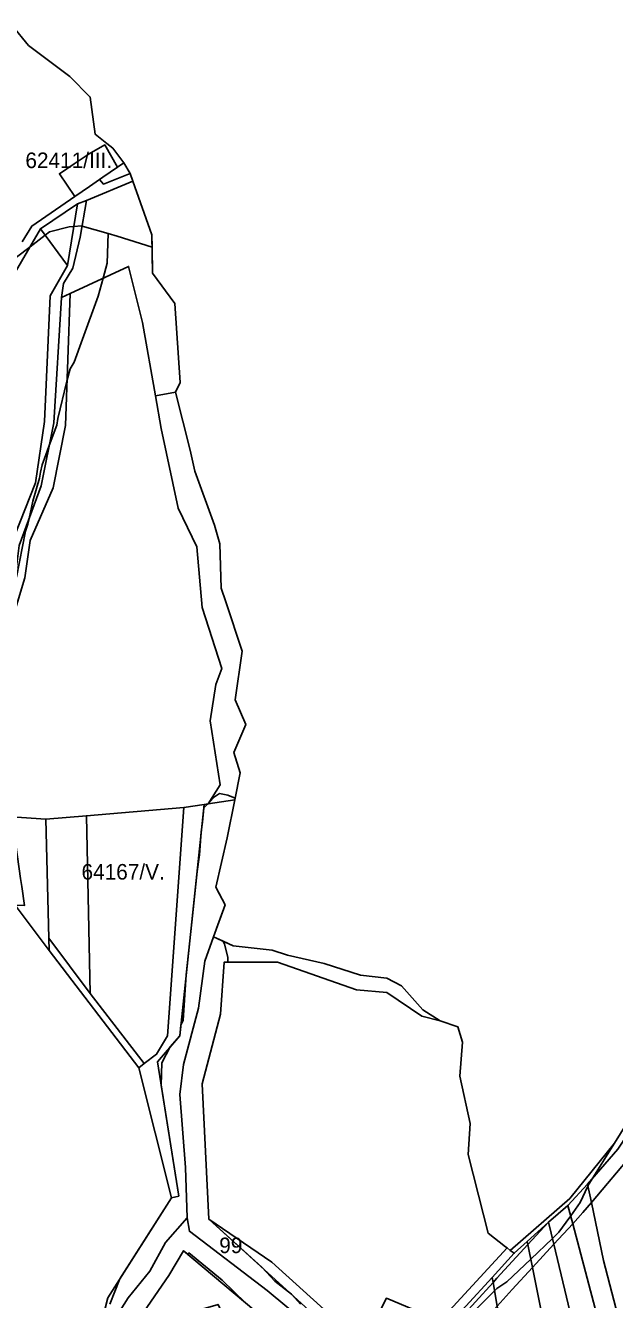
# Model space of a CAD drawing. Extents: x -502026 to -497664, y -1143484 to -1138019.
# Drawn here: x -499524 to -499221, y -1138994 to -1138339 of the extents above; entities that cross this region are included whole.
import ezdxf

# ---------------------------------------------------------------- set-up
doc = ezdxf.new("R2010")
doc.units = 0
for name, color, linetype in [('25', 7, 'Continuous'), ('37', 7, 'Continuous'), ('43', 7, 'Continuous'), ('55', 7, 'Continuous'), ('62', 7, 'Continuous'), ('7', 7, 'Continuous')]:
    doc.layers.add(name, color=color, linetype=linetype)

msp = doc.modelspace()

# ---------------------------------------------------------------- linework, layer by layer
at = {"layer": '25'}
msp.add_lwpolyline([(-499530.72, -1138338.78), (-499522.27, -1138349.07), (-499501.03, -1138365.08), (-499490.59, -1138375.59), (-499488.02, -1138394.73), (-499481.95, -1138399.48), (-499478.99, -1138401.8), (-499473.32, -1138409.43), (-499476.51, -1138411.63), (-499483.08, -1138400.19), (-499491.04, -1138404.76), (-499498.86, -1138409.97), (-499506.45, -1138415.02), (-499498.42, -1138426.7), (-499520.54, -1138441.91), (-499525.63, -1138450.02)], dxfattribs=at)
for points in [[(-499470.03, -1138414.97), (-499483.78, -1138420.33), (-499485.83, -1138418.04), (-499484.1, -1138416.85), (-499476.51, -1138411.63), (-499473.32, -1138409.43)], [(-499446.67, -1138527.4), (-499456.93, -1138529.27), (-499463.7, -1138491.52), (-499470.85, -1138462.66), (-499500.91, -1138476.52), (-499505.39, -1138478.58), (-499504.36, -1138471.49), (-499499.51, -1138463.57), (-499495.68, -1138447.61), (-499492.56, -1138428.73), (-499468.59, -1138418.83), (-499458.82, -1138446.46), (-499458.5, -1138466.16), (-499446.96, -1138481.75), (-499444.3, -1138522.32)], [(-499448.8, -1138941.59), (-499465.58, -1138874.76), (-499462.75, -1138872.57), (-499456.42, -1138867.8), (-499450.74, -1138858.41), (-499442.38, -1138740.98), (-499431.91, -1138739.41), (-499444.5, -1138858.39), (-499456.02, -1138871.76), (-499445.03, -1138940.74)], [(-499513.48, -1138746.91), (-499511.89, -1138808.1), (-499511.73, -1138814.39), (-499529.18, -1138791.22), (-499524.4, -1138791.35), (-499525.8, -1138781.59), (-499526.38, -1138777.45), (-499528.82, -1138760.16), (-499530.87, -1138745.67)], [(-499490.59, -1138836.55), (-499511.89, -1138808.1), (-499513.48, -1138746.91), (-499492.56, -1138745.17)]]:
    msp.add_lwpolyline(points, close=True, dxfattribs=at)
at = {"layer": '37'}
for points in [[(-499524.27, -1138622.83), (-499521.46, -1138603.68), (-499509.59, -1138576.6), (-499503.34, -1138544.42), (-499500.91, -1138476.52), (-499470.85, -1138462.66), (-499463.7, -1138491.52), (-499456.93, -1138529.27), (-499454.04, -1138546.01), (-499445.32, -1138587.05), (-499435.65, -1138606.87), (-499432.96, -1138638.09), (-499422.92, -1138669.37), (-499425.89, -1138677.59), (-499428.78, -1138696.38), (-499423.73, -1138729.2), (-499429.8, -1138739.09), (-499431.91, -1138739.41), (-499442.38, -1138740.98), (-499492.56, -1138745.17), (-499513.48, -1138746.91), (-499530.87, -1138745.67)], [(-499368.53, -1139000.61), (-499397.19, -1138974.7), (-499429.54, -1138952.6), (-499432.99, -1138883), (-499423.57, -1138847.18), (-499421.6, -1138820.45), (-499394.19, -1138820.45), (-499353.59, -1138834.76), (-499337.92, -1138836.13), (-499319.93, -1138848.22), (-499310.56, -1138850.57), (-499301.36, -1138853.71), (-499299, -1138861.57), (-499300.4, -1138879.14), (-499295.11, -1138903.36), (-499296.16, -1138919.34), (-499288.26, -1138950.44), (-499285.71, -1138959.88), (-499276.87, -1138966.81), (-499276.08, -1138967.42), (-499313.71, -1139008.25)], [(-499323.82, -1138999.2), (-499338.15, -1138993.28), (-499347.75, -1139011.93)]]:
    msp.add_lwpolyline(points, dxfattribs=at)
for points in [[(-499552.1, -1138790.55), (-499529.18, -1138791.22), (-499511.73, -1138814.39), (-499465.58, -1138874.76), (-499448.8, -1138941.59), (-499481.51, -1138993.07), (-499490.65, -1139028.16), (-499509.08, -1139023.11), (-499518.14, -1139024.19), (-499536.05, -1139033.29), (-499543.48, -1138994.87), (-499553.65, -1138932.11), (-499564.96, -1138868.79), (-499577.25, -1138815.93), (-499591.11, -1138774.54), (-499588.16, -1138761.99), (-499580.14, -1138748.95), (-499566.24, -1138743.1), (-499558.38, -1138790.37)], [(-499462.75, -1138872.57), (-499490.59, -1138836.55), (-499492.56, -1138745.17), (-499442.38, -1138740.98), (-499450.74, -1138858.41), (-499456.42, -1138867.8)], [(-499490.59, -1138836.55), (-499462.75, -1138872.57), (-499465.58, -1138874.76), (-499511.73, -1138814.39), (-499511.89, -1138808.1)], [(-499313.71, -1139008.25), (-499332.28, -1139026.34), (-499346.28, -1139036.83), (-499366.75, -1139009.62), (-499429.54, -1138952.6), (-499397.19, -1138974.7), (-499368.53, -1139000.61), (-499347.75, -1139011.93), (-499338.15, -1138993.28), (-499323.82, -1138999.2), (-499325.79, -1139003.8)], [(-499401.1, -1139003.69), (-499418.99, -1139008.62), (-499424.81, -1138996.42), (-499456.81, -1139005.71), (-499468.66, -1139018.24), (-499473.7, -1139021.67), (-499470.57, -1139011.19), (-499450.09, -1138981.53), (-499442.49, -1138968.89)]]:
    msp.add_lwpolyline(points, close=True, dxfattribs=at)
at = {"layer": '43'}
for points in [[(-499537.01, -1138745.37), (-499548.75, -1138698.77), (-499546.8, -1138675.05), (-499544.76, -1138664.32), (-499536.74, -1138644.34), (-499529, -1138621.3), (-499527.08, -1138606.23), (-499515.85, -1138575.58), (-499509.34, -1138543.14), (-499505.39, -1138478.58), (-499500.91, -1138476.52), (-499503.34, -1138544.42), (-499509.59, -1138576.6), (-499521.46, -1138603.68), (-499524.27, -1138622.83), (-499528.49, -1138637.04), (-499543.1, -1138676.2), (-499544.51, -1138699.06)], [(-499416.15, -1138737.03), (-499429.8, -1138739.09), (-499423.73, -1138729.2), (-499428.78, -1138696.38), (-499425.89, -1138677.59), (-499422.92, -1138669.37), (-499432.96, -1138638.09), (-499435.65, -1138606.87), (-499445.32, -1138587.05), (-499454.04, -1138546.01), (-499456.93, -1138529.27), (-499446.67, -1138527.4), (-499439.13, -1138557.09), (-499436.76, -1138567.96), (-499426.61, -1138595.74), (-499423.9, -1138605.27), (-499423.22, -1138628.12), (-499420.78, -1138635.17), (-499412.39, -1138660.5), (-499415.96, -1138685.51), (-499410.57, -1138698.3), (-499416.73, -1138712.67), (-499413.35, -1138723.05)], [(-499350.25, -1139039.81), (-499353.46, -1139042.22), (-499375.14, -1139022.61), (-499401.1, -1139003.69), (-499442.49, -1138968.89), (-499450.09, -1138981.53), (-499470.57, -1139011.19), (-499473.7, -1139021.67), (-499487.23, -1139030.88), (-499485.67, -1139023.72), (-499480.41, -1139008.06), (-499471.01, -1138993.06), (-499459.94, -1138979.29), (-499451.77, -1138964.63), (-499440.6, -1138951.93), (-499439.5, -1138958.87), (-499399.56, -1138989.3), (-499370.11, -1139013.65)]]:
    msp.add_lwpolyline(points, close=True, dxfattribs=at)
for points in [[(-499490.65, -1139028.16), (-499481.51, -1138993.07), (-499448.8, -1138941.59), (-499445.03, -1138940.74), (-499456.02, -1138871.76), (-499444.5, -1138858.39), (-499431.91, -1138739.41), (-499429.8, -1138739.09), (-499416.15, -1138737.03), (-499420.04, -1138756.44), (-499425.86, -1138781.93), (-499421.19, -1138790.99), (-499427.15, -1138807.36), (-499431.53, -1138819.97), (-499434.87, -1138844.05), (-499442.58, -1138873.14), (-499444.47, -1138888.57), (-499441.47, -1138925.97), (-499440.6, -1138951.93), (-499451.77, -1138964.63), (-499459.94, -1138979.29), (-499471.01, -1138993.06), (-499480.41, -1139008.06)], [(-499370.11, -1139013.65), (-499399.56, -1138989.3), (-499439.5, -1138958.87), (-499440.6, -1138951.93), (-499441.47, -1138925.97), (-499444.47, -1138888.57), (-499442.58, -1138873.14), (-499434.87, -1138844.05), (-499431.53, -1138819.97), (-499427.15, -1138807.36), (-499417.07, -1138812.03), (-499396.87, -1138814.31), (-499389, -1138816.85), (-499370.21, -1138821.17), (-499351.49, -1138827.06), (-499337.99, -1138828.75), (-499330.46, -1138832.65), (-499319.36, -1138844.97), (-499310.56, -1138850.57), (-499319.93, -1138848.22), (-499337.92, -1138836.13), (-499353.59, -1138834.76), (-499394.19, -1138820.45), (-499421.6, -1138820.45), (-499423.57, -1138847.18), (-499432.99, -1138883), (-499429.54, -1138952.6), (-499366.75, -1139009.62)]]:
    msp.add_lwpolyline(points, dxfattribs=at)
at = {"layer": '55'}
for points in [[(-499476.51, -1138411.63), (-499484.1, -1138416.85), (-499485.83, -1138418.04), (-499490.91, -1138421.53), (-499498.42, -1138426.7), (-499506.45, -1138415.02), (-499498.86, -1138409.97), (-499491.04, -1138404.76), (-499483.08, -1138400.19)], [(-499502.32, -1138462.17), (-499516.1, -1138443.28), (-499497.07, -1138430.58)], [(-499502.32, -1138462.17), (-499511.25, -1138477.75), (-499514.06, -1138542.37), (-499518.66, -1138574.05), (-499534.87, -1138614.79), (-499534.99, -1138618.61), (-499538.24, -1138616.75), (-499545.72, -1138612.49), (-499545.21, -1138605.34), (-499586.97, -1138559.44), (-499565.83, -1138540.79), (-499556.38, -1138512.27), (-499539.85, -1138477.89), (-499531.49, -1138469.59), (-499516.1, -1138443.28)], [(-499211.45, -1138919.07), (-499232.65, -1138944.1), (-499234.61, -1138934.63), (-499219.06, -1138916.54), (-499214.15, -1138909.07)], [(-499232.65, -1138944.1), (-499236.99, -1138949.22), (-499242.28, -1138954.93), (-499244.75, -1138945.59), (-499234.61, -1138934.63)], [(-499242.28, -1138954.93), (-499252.06, -1138965.49), (-499254.79, -1138954.09), (-499244.75, -1138945.59)], [(-499265.41, -1138965.63), (-499265.71, -1138964.12), (-499254.79, -1138954.09)], [(-499252.06, -1138965.49), (-499263.04, -1138977.44), (-499265.41, -1138965.63), (-499254.79, -1138954.09)], [(-499265.41, -1138965.63), (-499281.32, -1138982.93), (-499283.29, -1138985.11), (-499283.72, -1138982.6), (-499272.34, -1138970.18), (-499265.71, -1138964.12)], [(-499263.04, -1138977.44), (-499273.5, -1138988.83), (-499281.13, -1138997.36), (-499283.29, -1138985.11), (-499281.32, -1138982.93), (-499265.41, -1138965.63)], [(-499283.29, -1138985.11), (-499310.42, -1139015.06), (-499310.79, -1139012.14), (-499283.72, -1138982.6)], [(-499281.13, -1138997.36), (-499306, -1139025.17), (-499308.75, -1139028.21), (-499310.42, -1139015.06), (-499283.29, -1138985.11)]]:
    msp.add_lwpolyline(points, close=True, dxfattribs=at)
for points in [[(-499525.63, -1138450.02), (-499520.54, -1138441.91), (-499498.42, -1138426.7), (-499490.91, -1138421.53), (-499485.83, -1138418.04), (-499483.78, -1138420.33), (-499470.03, -1138414.97), (-499468.59, -1138418.83), (-499492.56, -1138428.73), (-499497.07, -1138430.58), (-499516.1, -1138443.28), (-499531.49, -1138469.59)], [(-499534.87, -1138614.79), (-499518.66, -1138574.05), (-499514.06, -1138542.37), (-499511.25, -1138477.75), (-499502.32, -1138462.17), (-499497.07, -1138430.58), (-499492.56, -1138428.73), (-499495.68, -1138447.61), (-499499.51, -1138463.57), (-499504.36, -1138471.49), (-499505.39, -1138478.58), (-499509.34, -1138543.14), (-499515.85, -1138575.58), (-499527.08, -1138606.23)], [(-499219.06, -1138916.54), (-499234.61, -1138934.63), (-499244.75, -1138945.59), (-499254.79, -1138954.09), (-499265.71, -1138964.12), (-499272.34, -1138970.18), (-499274.39, -1138968.75), (-499243.81, -1138942.05), (-499220.78, -1138913.59), (-499210.6, -1138897.3)], [(-499313.71, -1139008.25), (-499276.08, -1138967.42), (-499274.39, -1138968.75), (-499272.34, -1138970.18), (-499283.72, -1138982.6), (-499310.79, -1139012.14)]]:
    msp.add_lwpolyline(points, dxfattribs=at)
at = {"layer": '62'}
for points in [[(-499530.72, -1138338.78), (-499522.27, -1138349.07), (-499501.03, -1138365.08), (-499490.59, -1138375.59), (-499488.02, -1138394.73), (-499481.95, -1138399.48), (-499478.99, -1138401.8), (-499473.32, -1138409.43), (-499470.03, -1138414.97), (-499468.59, -1138418.83), (-499458.82, -1138446.46), (-499458.72, -1138452.71), (-499476.7, -1138447.19), (-499481.41, -1138445.75), (-499494.74, -1138441.95), (-499495, -1138441.87), (-499499, -1138442.19), (-499501.37, -1138442.37), (-499511.56, -1138444.87), (-499513.72, -1138446.54), (-499521.54, -1138452.58), (-499528.56, -1138458)], [(-499528.56, -1138458), (-499521.54, -1138452.58), (-499513.72, -1138446.54), (-499511.56, -1138444.87), (-499501.37, -1138442.37), (-499499, -1138442.19), (-499495, -1138441.87), (-499494.74, -1138441.95), (-499481.41, -1138445.75), (-499481.81, -1138461), (-499483.93, -1138468.69), (-499486.5, -1138478), (-499494.56, -1138500.12), (-499498.81, -1138512), (-499500.94, -1138515.37), (-499502.53, -1138521.74), (-499507.31, -1138540.87), (-499507.75, -1138544.25), (-499511.69, -1138554.83), (-499513.43, -1138559.52), (-499515.37, -1138564.75), (-499516.09, -1138568.5), (-499516.66, -1138571.5), (-499520.06, -1138583.37), (-499521.95, -1138592.23), (-499522.59, -1138595.25), (-499523.87, -1138598.75), (-499528.56, -1138622.5)], [(-499528.56, -1138622.5), (-499523.87, -1138598.75), (-499522.59, -1138595.25), (-499521.95, -1138592.23), (-499520.06, -1138583.37), (-499516.66, -1138571.5), (-499516.09, -1138568.5), (-499515.37, -1138564.75), (-499513.43, -1138559.52), (-499511.69, -1138554.83), (-499507.75, -1138544.25), (-499507.31, -1138540.87), (-499502.53, -1138521.74), (-499500.94, -1138515.37), (-499498.81, -1138512), (-499494.56, -1138500.12), (-499486.5, -1138478), (-499483.93, -1138468.69), (-499481.81, -1138461), (-499481.41, -1138445.75), (-499476.7, -1138447.19), (-499458.72, -1138452.71), (-499458.5, -1138466.16), (-499446.96, -1138481.75), (-499444.3, -1138522.32), (-499446.67, -1138527.4), (-499439.13, -1138557.09), (-499436.76, -1138567.96), (-499426.61, -1138595.74), (-499423.9, -1138605.27), (-499423.22, -1138628.12), (-499420.78, -1138635.17), (-499412.39, -1138660.5), (-499415.96, -1138685.51), (-499410.57, -1138698.3), (-499416.73, -1138712.67), (-499413.35, -1138723.05), (-499415.97, -1138736.14), (-499419.78, -1138734.62), (-499424.03, -1138733.75), (-499426.59, -1138735.5), (-499429.23, -1138738.17), (-499429.8, -1138739.09), (-499430.21, -1138739.15), (-499432.08, -1138741.05), (-499432.87, -1138748.48), (-499433.4, -1138753.46), (-499434.25, -1138765.25), (-499435.55, -1138773.78), (-499438.32, -1138799.95), (-499441.18, -1138827.04), (-499442.72, -1138850.25), (-499443.91, -1138852.82), (-499444.5, -1138858.39), (-499449.38, -1138864.06), (-499453.78, -1138872.25), (-499454.11, -1138883.76), (-499445.03, -1138940.74), (-499448.8, -1138941.59), (-499475.34, -1138983.36), (-499480.53, -1138996.37)], [(-499480.53, -1138996.37), (-499475.34, -1138983.36), (-499448.8, -1138941.59), (-499445.03, -1138940.74), (-499454.11, -1138883.76), (-499453.78, -1138872.25), (-499449.38, -1138864.06), (-499444.5, -1138858.39), (-499443.91, -1138852.82), (-499442.72, -1138850.25), (-499441.18, -1138827.04), (-499438.32, -1138799.95), (-499435.55, -1138773.78), (-499434.25, -1138765.25), (-499433.4, -1138753.46), (-499432.87, -1138748.48), (-499432.08, -1138741.05), (-499430.21, -1138739.15), (-499429.8, -1138739.09), (-499429.23, -1138738.17), (-499426.59, -1138735.5), (-499424.03, -1138733.75), (-499419.78, -1138734.62), (-499415.97, -1138736.14), (-499416.15, -1138737.03), (-499420.04, -1138756.44), (-499425.86, -1138781.93), (-499425.54, -1138782.55), (-499421.19, -1138790.99), (-499424.94, -1138801.28), (-499427.15, -1138807.36), (-499422.13, -1138809.69), (-499421.5, -1138811.12), (-499419.78, -1138817.87), (-499419.78, -1138820.45), (-499421.6, -1138820.45), (-499423.57, -1138847.18), (-499432.99, -1138883), (-499429.54, -1138952.6), (-499402.32, -1138977.32), (-499395.56, -1138984.5), (-499387.06, -1138991.25), (-499382.41, -1138996.37)], [(-499382.41, -1138996.37), (-499387.06, -1138991.25), (-499395.56, -1138984.5), (-499402.32, -1138977.32), (-499429.54, -1138952.6), (-499432.99, -1138883), (-499423.57, -1138847.18), (-499421.6, -1138820.45), (-499419.78, -1138820.45), (-499419.78, -1138817.87), (-499421.5, -1138811.12), (-499422.13, -1138809.69), (-499417.07, -1138812.03), (-499396.87, -1138814.31), (-499389, -1138816.85), (-499370.21, -1138821.17), (-499351.49, -1138827.06), (-499337.99, -1138828.75), (-499330.46, -1138832.65), (-499319.36, -1138844.97), (-499310.56, -1138850.57), (-499301.36, -1138853.71), (-499299, -1138861.57), (-499300.4, -1138879.14), (-499295.11, -1138903.36), (-499296.16, -1138919.34), (-499288.26, -1138950.44), (-499285.71, -1138959.88), (-499276.87, -1138966.81), (-499276.08, -1138967.42), (-499274.39, -1138968.75), (-499243.81, -1138942.05), (-499220.78, -1138913.59), (-499234.44, -1138935.45), (-499234.56, -1138935.62), (-499238.37, -1138944.12), (-499243.33, -1138950.96), (-499245.59, -1138954.08), (-499249.44, -1138959.37), (-499251.11, -1138960.97), (-499252.76, -1138962.55), (-499263.9, -1138973.16), (-499276.19, -1138984.87), (-499281.28, -1138988.25), (-499282.52, -1138989.48), (-499293.19, -1139000.12)], [(-499293.19, -1139000.12), (-499282.52, -1138989.48), (-499281.28, -1138988.25), (-499276.19, -1138984.87), (-499263.9, -1138973.16), (-499252.76, -1138962.55), (-499251.11, -1138960.97), (-499249.44, -1138959.37), (-499245.59, -1138954.08), (-499243.33, -1138950.96), (-499238.37, -1138944.12), (-499234.56, -1138935.62), (-499234.44, -1138935.45), (-499220.78, -1138913.59), (-499210.6, -1138897.3)], [(-499470.57, -1139011.19), (-499450.09, -1138981.53), (-499442.49, -1138968.89), (-499440.21, -1138970.81), (-499439.75, -1138970), (-499422.75, -1138984), (-499410.72, -1138995.6)], [(-499410.72, -1138995.6), (-499422.75, -1138984), (-499439.75, -1138970), (-499440.21, -1138970.81), (-499442.49, -1138968.89), (-499450.09, -1138981.53), (-499470.57, -1139011.19)]]:
    msp.add_lwpolyline(points, dxfattribs=at)
at = {"layer": '7'}
for points in [[(-499180.76, -1139022.59), (-499205.02, -1139056.09), (-499226.5, -1138973.8), (-499232.65, -1138944.1), (-499211.45, -1138919.07)], [(-499205.02, -1139056.09), (-499212.76, -1139066.77), (-499242.28, -1138954.93), (-499236.99, -1138949.22), (-499232.65, -1138944.1), (-499226.5, -1138973.8)], [(-499212.76, -1139066.77), (-499224.08, -1139082.4), (-499252.06, -1138965.49), (-499242.28, -1138954.93)], [(-499224.08, -1139082.4), (-499236.77, -1139099.91), (-499248.23, -1139051.22), (-499263.04, -1138977.44), (-499252.06, -1138965.49)], [(-499236.77, -1139099.91), (-499241.77, -1139106.82), (-499255.51, -1139119.18), (-499258.03, -1139120.75), (-499267.72, -1139073.42), (-499281.13, -1138997.36), (-499273.5, -1138988.83), (-499263.04, -1138977.44), (-499248.23, -1139051.22)]]:
    msp.add_lwpolyline(points, close=True, dxfattribs=at)

# ---------------------------------------------------------------- texts
at = {"layer": '62'}
for s, p in [('62411/III.', (-499523.93, -1138412.11)), ('64167/V.', (-499495.04, -1138777.99)), ('99', (-499424.18, -1138970.08))]:
    msp.add_text(s, height=8, dxfattribs=at).set_placement(p)

doc.saveas('drawing.dxf')
